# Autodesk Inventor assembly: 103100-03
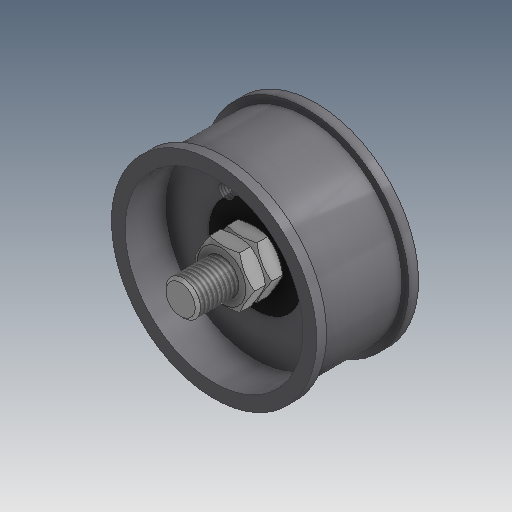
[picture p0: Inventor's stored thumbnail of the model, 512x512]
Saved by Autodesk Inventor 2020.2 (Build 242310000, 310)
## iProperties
Created: 2000-10
Part Number: 103100-03
Document SubType Name: Assembly
Designer: wymerj
Mass: 1567.08 g
Surface Area: 535.621 cm^2
Volume: 199.786 cm^3
Density: 7.84377 g/cm^3
Control State: 0
Master: False
Checked Out: False
Shininess: 0.0
Length Units: 11269
Angle Units: 11279
Time Units: 11290
Mass Units: 11283
Length Display Precision: 3
Angle Display Precision: 2
Compacted: True
Dimensions: 103,1x70x103,1 mm
Mass: 1,567 kg
DocNumber: 103100-03.iam
Folder: 01 - Themengebiete\Simplification\01 - Packaging machine\
VDS_Category: 3D Komponenten
Density: 0.0
Volumn: 0.0
Area: 0.0
PropertySet Name: Model Information
Author: wymerj
Revision Number: -
Title: belt wheel
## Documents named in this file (5)
- D:\07 - DEMODATEN\OTX 2019 - Dataset - UPDATE - Dez2019\Designs\07-Packing machine\103100-03.iam
- D:\07 - DEMODATEN\OTX 2019 - Dataset - UPDATE - Dez2019\Designs\07-Packing machine\A104989.iam
- D:\07 - DEMODATEN\OTX 2019 - Dataset - UPDATE - Dez2019\Designs\07-Packing machine\Parts\ADSK-011781.ipt
- D:\07 - DEMODATEN\OTX 2019 - Dataset - UPDATE - Dez2019\Content Center Files\de-DE\ISO 2338(2)\ISO 2338 - 10 m6 x 18.ipt
- D:\07 - DEMODATEN\OTX 2019 - Dataset - UPDATE - Dez2019\Content Center Files\de-DE\ISO 4026\ISO 4026 - M8 x 16 - ISO.ipt
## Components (5 placed, 4 different names)
1. A104989:1 [sub-assembly] — Flush:1, Mate:1, Mate:2
2. ADSK-011781:1 — Flush:1, Mate:1, Mate:2, Einfügen:1, Einfügen:2
3. ISO 2338 10 m6 x 18:1 — Einfügen:1
4. ISO 2338 10 m6 x 18:2 — Einfügen:2
5. ISO 4026 M8 x 16:1
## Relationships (5: Mate 2, Insert 2, Flush 1)
- Flush:1: A104989:1 ↔ ADSK-011781:1
- Mate:1: A104989:1 ↔ ADSK-011781:1
- Mate:2: A104989:1 ↔ ADSK-011781:1
- Einfügen:1 [Insert]: ADSK-011781:1 ↔ ISO 2338 10 m6 x 18:1
- Einfügen:2 [Insert]: ADSK-011781:1 ↔ ISO 2338 10 m6 x 18:2
